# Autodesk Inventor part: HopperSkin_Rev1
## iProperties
Created: 2009-01
Part Number: HopperSkin_Rev1
Document SubType Name: Modeling
Designer: claivier
Norme de conversion: STEP AP214IS
Nom du fichier: HopperSkin_Rev1.STEP
Préprocesseur: SolidWorks 2008
Postprocesseur: Build: 344a, Release: 11 SP2 - Date: Fri 08/18/2006
Unités envoyées: INCHES
Incertitude: 1e-05
Author: claivier
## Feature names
1. Base1
